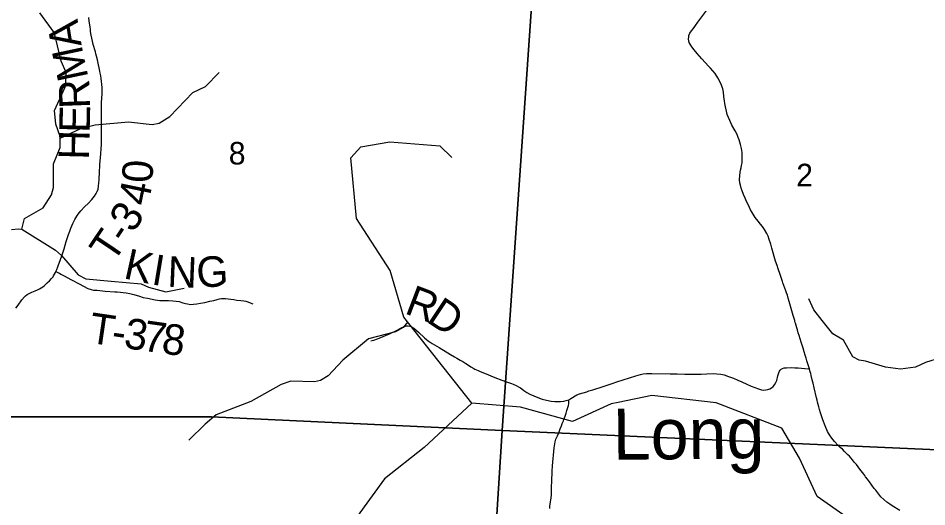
# Model space of a CAD drawing. Extents: x 0 to 34, y 0 to 22.
# Drawn here: x 4.109 to 5.797, y 16.841 to 17.749 of the extents above; entities that cross this region are included whole.
import ezdxf

# ---------------------------------------------------------------- set-up
doc = ezdxf.new("R2010")
doc.units = 0
for name, color, linetype in [('GM_X_County_Road', 7, 'Continuous'), ('GM_X_Minor_River', 7, 'Continuous'), ('GM_X_Minor_River_Text', 7, 'Continuous'), ('GM_X_Section', 7, 'Continuous'), ('GM_X_Section_Text', 7, 'Continuous'), ('GM_X_Township_Road', 7, 'Continuous'), ('GM_X_Township_Road_Text', 7, 'Continuous')]:
    doc.layers.add(name, color=color, linetype=linetype)

msp = doc.modelspace()

# ---------------------------------------------------------------- linework, layer by layer
at = {"layer": 'GM_X_County_Road'}
msp.add_lwpolyline([(5.7466, 16.8346), (5.7324, 16.8435), (5.7278, 16.8467), (5.7227, 16.8503), (5.7168, 16.855), (5.7114, 16.8602), (5.7054, 16.8674), (5.7018, 16.8721), (5.699, 16.8758), (5.6945, 16.8818), (5.6904, 16.8876), (5.6867, 16.8928), (5.6831, 16.8973), (5.6813, 16.8995), (5.6796, 16.9019), (5.6748, 16.9082), (5.6703, 16.9141), (5.6692, 16.9156), (5.6658, 16.9199), (5.6638, 16.9224), (5.6618, 16.9247), (5.6588, 16.9286), (5.6556, 16.9324), (5.6529, 16.9353), (5.65, 16.9383), (5.6466, 16.9412), (5.6435, 16.9444), (5.64, 16.9483), (5.636, 16.9519), (5.6321, 16.9554), (5.6251, 16.9627), (5.62, 16.969), (5.6158, 16.9753), (5.6125, 16.9813), (5.6079, 16.9916), (5.6034, 17.0032), (5.5992, 17.0163), (5.5975, 17.0222), (5.5961, 17.027), (5.5938, 17.036), (5.5929, 17.0396), (5.5919, 17.0438), (5.5876, 17.0625), (5.5856, 17.0709), (5.585, 17.0733), (5.584, 17.0775), (5.5821, 17.0853), (5.5812, 17.0889), (5.5802, 17.0924), (5.579, 17.0966), (5.5786, 17.0978), (5.5758, 17.1072), (5.5741, 17.1126), (5.5727, 17.1173), (5.5708, 17.1232), (5.569, 17.1292), (5.5667, 17.1363), (5.5651, 17.1416), (5.5632, 17.1475), (5.5614, 17.1535), (5.5595, 17.1594), (5.5579, 17.1647), (5.5563, 17.17), (5.5551, 17.1742), (5.5539, 17.1783), (5.5528, 17.1823), (5.5524, 17.1839), (5.5518, 17.1861), (5.5513, 17.1877), (5.5487, 17.1966), (5.5413, 17.2227), (5.5393, 17.229), (5.5376, 17.2345), (5.536, 17.2391), (5.5348, 17.2426), (5.5313, 17.2525), (5.5294, 17.2578), (5.5286, 17.2601), (5.5274, 17.2635), (5.5259, 17.2677), (5.5245, 17.273), (5.5207, 17.2834), (5.5186, 17.2898), (5.5159, 17.298), (5.5134, 17.3066), (5.5115, 17.3132), (5.509, 17.3219), (5.5069, 17.3292), (5.5041, 17.338), (5.5017, 17.344), (5.4994, 17.3489), (5.4951, 17.3563), (5.4913, 17.3621), (5.4876, 17.3667), (5.4832, 17.3723), (5.4781, 17.379), (5.4742, 17.3848), (5.472, 17.3883), (5.469, 17.3932), (5.4652, 17.4015), (5.462, 17.4086), (5.4594, 17.4149), (5.4562, 17.4215), (5.4534, 17.4287), (5.4519, 17.4334), (5.4504, 17.4387), (5.4492, 17.4435), (5.4488, 17.4488), (5.4491, 17.4566), (5.45, 17.4622), (5.4508, 17.4669), (5.4517, 17.4711), (5.4526, 17.4757), (5.4534, 17.4806), (5.4539, 17.4864), (5.4539, 17.4942), (5.4534, 17.4997), (5.4524, 17.5073), (5.4505, 17.5143), (5.4493, 17.5186), (5.448, 17.5234), (5.4465, 17.5273), (5.445, 17.5314), (5.4429, 17.5354), (5.4407, 17.5398), (5.4347, 17.5502), (5.4305, 17.5593), (5.426, 17.5702), (5.4243, 17.5763), (5.4225, 17.5844), (5.4215, 17.5908), (5.4208, 17.5957), (5.4198, 17.6037), (5.4189, 17.6115), (5.4177, 17.6179), (5.4156, 17.6246), (5.4125, 17.6317), (5.4087, 17.6386), (5.4035, 17.6463), (5.3991, 17.6516), (5.3949, 17.6562), (5.3911, 17.6602), (5.3847, 17.667), (5.3788, 17.6734), (5.3704, 17.6833), (5.3645, 17.6905), (5.3602, 17.6959), (5.357, 17.7006), (5.3554, 17.7041), (5.3545, 17.7072), (5.3541, 17.7104), (5.3544, 17.7143), (5.3549, 17.7168), (5.3566, 17.721), (5.3579, 17.7232), (5.3602, 17.7262), (5.3621, 17.7289), (5.3646, 17.7321), (5.3669, 17.7356), (5.3714, 17.7415), (5.3769, 17.7491), (5.388, 17.7639)], dxfattribs=at)
at = {"layer": 'GM_X_Minor_River'}
for points in [[(4.0962, 17.3564), (4.1094, 17.3576), (4.1159, 17.3572), (4.1208, 17.377), (4.1553, 17.3971), (4.1709, 17.4207), (4.1743, 17.4344), (4.1747, 17.4785), (4.1868, 17.509), (4.1868, 17.5291), (4.1785, 17.5523), (4.1766, 17.5778), (4.1956, 17.62), (4.1975, 17.6265), (4.1979, 17.6485), (4.1884, 17.669), (4.1789, 17.7108), (4.1759, 17.7226), (4.149, 17.7591)], [(4.1868, 17.5265), (4.2253, 17.5439), (4.2516, 17.5511), (4.3136, 17.5563), (4.3579, 17.5516), (4.3709, 17.554), (4.3908, 17.5667), (4.4332, 17.6109), (4.4566, 17.622), (4.4824, 17.6483)], [(4.9518, 17.0338), (4.8254, 17.1937), (4.7996, 17.2807), (4.7372, 17.377), (4.7266, 17.49), (4.7453, 17.5099), (4.7995, 17.5195), (4.8922, 17.512), (4.9142, 17.4905)], [(4.1159, 17.3572), (4.178, 17.318), (4.1896, 17.3084), (4.2203, 17.2722), (4.2346, 17.2648), (4.2816, 17.2604), (4.337, 17.2558), (4.3506, 17.2492), (4.3828, 17.2411), (4.4171, 17.2479)], [(6.1218, 17.1925), (6.0866, 17.1832), (6.0639, 17.179), (6.037, 17.1664), (5.9975, 17.1424), (5.9771, 17.1371), (5.9464, 17.1393), (5.9191, 17.1332), (5.8978, 17.1347), (5.8781, 17.1423), (5.8637, 17.1411), (5.822, 17.1179), (5.794, 17.1095), (5.7758, 17.1011), (5.7477, 17.0969), (5.7197, 17.1011), (5.6825, 17.112), (5.6711, 17.1139), (5.659, 17.12), (5.642, 17.1508), (5.6219, 17.1626), (5.6026, 17.1876), (5.587, 17.2074), (5.5776, 17.2275)], [(4.8324, 17.1849), (4.824, 17.1743), (4.8098, 17.1665), (4.7595, 17.1535), (4.7118, 17.1139), (4.6848, 17.0846), (4.6707, 17.076), (4.6592, 17.0735), (4.6156, 17.0749), (4.5976, 17.0687), (4.5413, 17.0372), (4.4768, 17.0126), (4.456, 16.995), (4.4256, 16.9654)], [(5.8267, 16.659), (5.7806, 16.7611), (5.6944, 16.7896), (5.5932, 16.8604), (5.56, 16.9319), (5.5274, 16.9877), (5.4057, 17.0349), (5.2859, 17.0482), (5.2231, 17.0355), (5.2102, 17.0327), (5.1385, 16.9998), (5.0417, 17.0267), (4.9517, 17.0338), (4.8632, 16.9514), (4.7891, 16.8935), (4.7108, 16.785), (4.674, 16.7535), (4.5957, 16.7346), (4.5258, 16.6805), (4.4927, 16.6266)]]:
    msp.add_lwpolyline(points, dxfattribs=at)
at = {"layer": 'GM_X_Section'}
for points in [[(4.0202, 18.0387), (4.4977, 18.0162), (5.0782, 18.0036), (5.0081, 16.9831), (4.4681, 17.0085), (3.9555, 17.0086), (3.9833, 17.4262), (4.01, 17.8394)], [(5.0782, 18.0036), (6.1294, 17.9583), (6.1188, 17.7931), (6.0808, 17.1618), (6.0674, 16.9363), (5.0081, 16.9831)], [(5.0081, 16.9831), (4.9447, 15.9846), (3.8924, 16.0203), (3.9555, 17.0086), (4.4681, 17.0085)], [(6.0674, 16.9363), (6.0506, 16.6748), (6.0049, 15.9328), (4.9568, 15.9843), (4.9447, 15.9846), (5.0081, 16.9831)]]:
    msp.add_lwpolyline(points, close=True, dxfattribs=at)
at = {"layer": 'GM_X_Township_Road'}
for points in [[(4.1046, 17.2102), (4.109, 17.2161), (4.1157, 17.2258), (4.1203, 17.2315), (4.1226, 17.2336), (4.1253, 17.2357), (4.129, 17.2379), (4.1318, 17.2392), (4.1342, 17.2404), (4.1374, 17.2415), (4.1405, 17.2424), (4.1448, 17.2444), (4.1485, 17.2464), (4.1544, 17.25), (4.1575, 17.2526), (4.1602, 17.2551), (4.1629, 17.2575), (4.1667, 17.261), (4.1707, 17.2654), (4.172, 17.267), (4.1736, 17.2689), (4.1747, 17.2706), (4.1763, 17.2736), (4.178, 17.2768), (4.1789, 17.2788), (4.1805, 17.2824), (4.1824, 17.2875), (4.1837, 17.291), (4.1866, 17.2991), (4.1904, 17.3097), (4.1923, 17.3154), (4.1941, 17.3209), (4.198, 17.334), (4.2, 17.3401), (4.2024, 17.3475), (4.2047, 17.3535), (4.2068, 17.3591), (4.2104, 17.3676), (4.2141, 17.3754), (4.2175, 17.3813), (4.2204, 17.3853), (4.2255, 17.3915), (4.2322, 17.3988), (4.2392, 17.4058), (4.2456, 17.4125), (4.2508, 17.4187), (4.2539, 17.4234), (4.2558, 17.4273), (4.2572, 17.4315), (4.2582, 17.437), (4.2589, 17.4432), (4.2591, 17.4485), (4.2594, 17.4538), (4.2596, 17.4594), (4.2598, 17.4637), (4.26, 17.4661), (4.2605, 17.4725), (4.2608, 17.4779), (4.2617, 17.4899), (4.2635, 17.5143), (4.2639, 17.5345), (4.2639, 17.5412), (4.2637, 17.5517), (4.2636, 17.5554), (4.2634, 17.5659), (4.2636, 17.5833), (4.2638, 17.5919), (4.2642, 17.6011), (4.2646, 17.6078), (4.2649, 17.6134), (4.2647, 17.6198), (4.2643, 17.6263), (4.2637, 17.6318), (4.2627, 17.6373), (4.2621, 17.6422), (4.2611, 17.647), (4.2604, 17.6507), (4.2593, 17.6567), (4.2582, 17.6622), (4.2559, 17.6715), (4.2543, 17.6786), (4.2533, 17.6831), (4.2525, 17.6866), (4.2484, 17.7), (4.2468, 17.7066), (4.2456, 17.712), (4.2446, 17.7175), (4.2434, 17.7242), (4.2429, 17.7279), (4.2423, 17.7328), (4.2408, 17.7437), (4.2399, 17.7506)], [(4.1789, 17.2788), (4.184, 17.2762), (4.1855, 17.2753), (4.1882, 17.2739), (4.1931, 17.2712), (4.2078, 17.2632), (4.2223, 17.2558), (4.2385, 17.2472), (4.2443, 17.2449), (4.2489, 17.244), (4.2557, 17.2436), (4.2707, 17.2422), (4.2886, 17.241), (4.2924, 17.2407), (4.299, 17.2403), (4.3037, 17.2398), (4.3093, 17.2392), (4.316, 17.2379), (4.3237, 17.2357), (4.3339, 17.2326), (4.3408, 17.2305), (4.3491, 17.2291), (4.3632, 17.2259), (4.3721, 17.2246), (4.38, 17.2244), (4.3883, 17.2245), (4.3961, 17.2243), (4.4024, 17.2237), (4.4081, 17.2227), (4.4148, 17.2206), (4.4195, 17.2193), (4.4236, 17.2184), (4.4288, 17.2175), (4.4344, 17.2177), (4.4405, 17.2186), (4.4472, 17.2199), (4.4553, 17.2212), (4.4648, 17.2232), (4.4724, 17.2249), (4.4782, 17.2266), (4.483, 17.2279), (4.4863, 17.2285), (4.4897, 17.2287), (4.4942, 17.2285), (4.4986, 17.2278), (4.504, 17.227), (4.5095, 17.2263), (4.5153, 17.2255), (4.5226, 17.2246), (4.5281, 17.2238), (4.5319, 17.2232), (4.5355, 17.2222), (4.54, 17.2204), (4.5447, 17.2183)], [(4.7638, 17.1495), (4.7666, 17.1502), (4.7697, 17.1511), (4.7761, 17.1535), (4.7794, 17.1549), (4.7984, 17.1625), (4.8128, 17.1698), (4.8216, 17.1745), (4.8262, 17.1764), (4.831, 17.1776), (4.8334, 17.1777), (4.8364, 17.1771), (4.8399, 17.1756), (4.8437, 17.1733), (4.8476, 17.1701), (4.8522, 17.1659), (4.8636, 17.1555), (4.8675, 17.1523), (4.8704, 17.15), (4.878, 17.1447), (4.8908, 17.1371), (4.9116, 17.1247), (4.9196, 17.12), (4.9239, 17.1175), (4.9297, 17.114), (4.9346, 17.1111), (4.9401, 17.1076), (4.9454, 17.1043), (4.9498, 17.1015), (4.9551, 17.0984), (4.9574, 17.0973), (4.96, 17.0959), (4.9634, 17.0944), (4.9669, 17.093), (4.9749, 17.0897), (4.9944, 17.0818), (5.0072, 17.077), (5.0159, 17.0738), (5.0212, 17.0719), (5.0252, 17.0703), (5.0281, 17.0693), (5.0338, 17.0669), (5.0381, 17.0645), (5.0418, 17.0622), (5.0442, 17.0604), (5.0479, 17.0578), (5.0535, 17.0541), (5.0595, 17.0509), (5.067, 17.0475), (5.0742, 17.0443), (5.0822, 17.0414), (5.09, 17.0395), (5.0986, 17.038), (5.1057, 17.0374), (5.1111, 17.0371), (5.1163, 17.0371), (5.1222, 17.0379), (5.1269, 17.0391), (5.1316, 17.0405)], [(5.1316, 17.0405), (5.1352, 17.0424), (5.1387, 17.0445), (5.1437, 17.0476), (5.1468, 17.0494), (5.1514, 17.0511), (5.1585, 17.0534), (5.165, 17.0553), (5.1691, 17.0566), (5.1762, 17.0588), (5.1821, 17.0608), (5.1898, 17.0633), (5.214, 17.0713), (5.2211, 17.0736), (5.2441, 17.081), (5.256, 17.0848), (5.2648, 17.0875), (5.2696, 17.0885), (5.2757, 17.0889), (5.2856, 17.089), (5.3198, 17.0885), (5.3329, 17.0882), (5.3471, 17.088), (5.362, 17.0879), (5.3776, 17.0881), (5.3879, 17.0885), (5.4011, 17.0889), (5.4067, 17.0887), (5.414, 17.0877), (5.42, 17.0864), (5.4283, 17.0838), (5.4375, 17.0802), (5.4454, 17.0767), (5.4528, 17.0734), (5.4622, 17.0693), (5.4705, 17.0657), (5.4838, 17.0605), (5.4893, 17.0589), (5.493, 17.0584), (5.4974, 17.0585), (5.5012, 17.0592), (5.5048, 17.0605), (5.5081, 17.0625), (5.511, 17.0649), (5.5139, 17.0683), (5.5162, 17.0721), (5.5178, 17.0762), (5.52, 17.0847), (5.5216, 17.0906), (5.5229, 17.0933), (5.5242, 17.0952), (5.526, 17.0969), (5.5285, 17.0984), (5.532, 17.0994), (5.5362, 17.0999), (5.5448, 17.1), (5.5517, 17.0998), (5.5578, 17.0995), (5.5701, 17.0985), (5.5786, 17.0978)], [(5.0963, 16.8382), (5.0967, 16.8425), (5.0971, 16.8465), (5.0975, 16.8505), (5.098, 16.8546), (5.0986, 16.8577), (5.0993, 16.8641), (5.0995, 16.867), (5.0997, 16.8728), (5.1003, 16.8942), (5.1005, 16.902), (5.1007, 16.9079), (5.1014, 16.9175), (5.1046, 16.9508), (5.1055, 16.9585), (5.1061, 16.9621), (5.1067, 16.9646), (5.1076, 16.9674), (5.1105, 16.9736), (5.1132, 16.9792), (5.1159, 16.9861), (5.1181, 16.9919), (5.1196, 16.996), (5.1216, 17.0011), (5.1225, 17.0034), (5.1248, 17.0098), (5.1268, 17.0157), (5.1283, 17.0204), (5.1309, 17.0294), (5.1317, 17.0334), (5.1318, 17.0369), (5.1316, 17.0405)]]:
    msp.add_lwpolyline(points, dxfattribs=at)

# ---------------------------------------------------------------- texts
at = {"layer": 'GM_X_Minor_River_Text'}
msp.add_text('Long', height=0.0947, rotation=0.5112, dxfattribs=at).set_placement((5.2137, 16.9288))
at = {"layer": 'GM_X_Section_Text'}
for s, p in [('8', (4.5, 17.4773)), ('2', (5.5541, 17.4368))]:
    msp.add_text(s, height=0.0419, rotation=0, dxfattribs=at).set_placement(p)
at = {"layer": 'GM_X_Township_Road_Text'}
for s, rotation, p in [('A', 98.976, (4.2268, 17.6987)), ('M', 101.9764, (4.2394, 17.6391)), ('R', 92.1144, (4.2425, 17.5819)), ('E', 88.7221, (4.2416, 17.5358)), ('H', 88.6192, (4.2403, 17.4857)), ('0', 86.9958, (4.358, 17.4422)), ('4', 78.2462, (4.3497, 17.3985)), ('3', 57.8282, (4.3228, 17.3485)), ('T', 56.159, (4.2852, 17.2923)), ('-', 56.2662, (4.3089, 17.3277)), ('K', 347.5755, (4.3027, 17.2664)), ('I', 350.5159, (4.3547, 17.255)), ('N', 357.5849, (4.3853, 17.2504)), ('G', 3.4121, (4.4416, 17.2483)), ('R', 339.131, (4.8246, 17.2014)), ('D', 326.4024, (4.8653, 17.1863)), ('T', 351.6566, (4.2382, 17.1465)), ('3', 351.7154, (4.3034, 17.1369)), ('7', 351.8574, (4.3382, 17.1318)), ('8', 352.3329, (4.3734, 17.1268)), ('-', 351.663, (4.2803, 17.1403))]:
    msp.add_text(s, height=0.0568, rotation=rotation, dxfattribs=at).set_placement(p)

doc.saveas('drawing.dxf')
